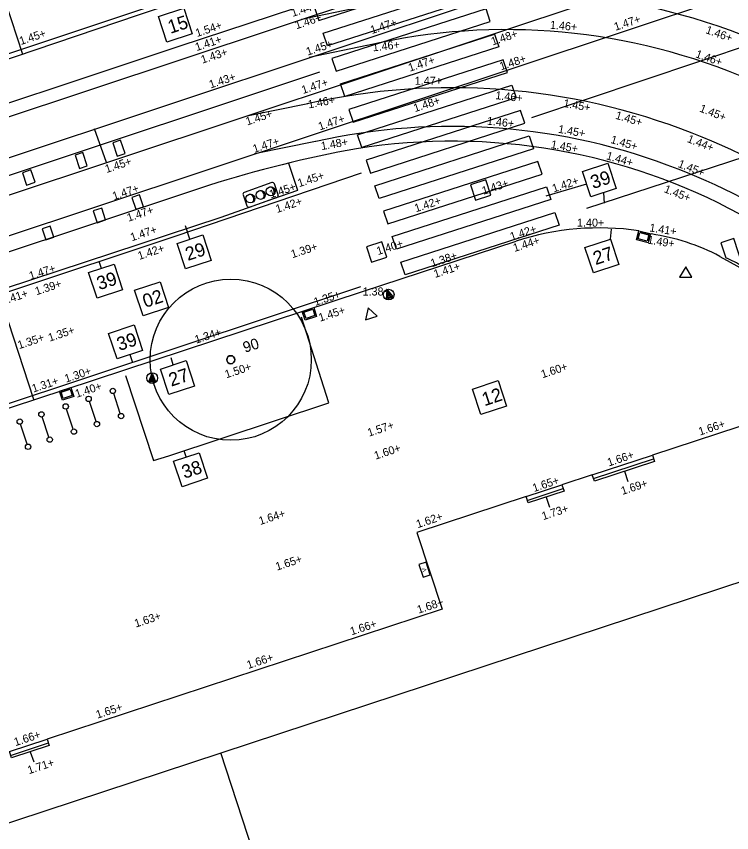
# Model space of a CAD drawing. Extents: x 122462 to 123306, y 485548 to 486417.
# Drawn here: x 122777.58 to 122804.23, y 486142.72 to 486173.11 of the extents above; entities that cross this region are included whole.
import ezdxf

# ---------------------------------------------------------------- set-up
doc = ezdxf.new("R2010")
doc.units = 0
for name, color, linetype in [('B nummers', 7, 'Continuous'), ('B-WE-AL-WERKGRENS-G', 7, 'Continuous'), ('B-WE-GR-BOOM-S', 7, 'Continuous'), ('B-WE-GR-BOOM_BOOMDIAMETER', 7, 'Continuous'), ('B-WE-KL-DATA_TELECOM_KAST-S', 7, 'Continuous'), ('B-WE-OG-HOOGTEPUNT-S', 7, 'Continuous'), ('B-WE-OG-TOPOGRAFIE_GEVELDETAIL-G', 7, 'Continuous'), ('B-WE-OG-TOPOKAART-G', 7, 'Continuous'), ('B-WE-VH-KANTOPSLUITING_TROTTOIRBAND', 7, 'Continuous'), ('Level 4', 7, 'Continuous'), ('V boomranden staal', 7, 'Continuous'), ('V Hoogtelijn', 7, 'Continuous'), ('V markering 1-1 10 cm', 7, 'Continuous'), ('V markering figuratie', 7, 'Continuous'), ('V markering ononderbroken streep 10 cm', 7, 'Continuous'), ('V materiaalscheiding algemeen', 7, 'Continuous'), ('V meubilair fietsenrek', 7, 'Continuous'), ('V meubilair trammast', 7, 'Continuous'), ('V meubilair verkeersbord', 7, 'Continuous'), ('V meubilair verkeerslicht', 7, 'Continuous'), ('V Rails', 7, 'Continuous'), ('V riool putdeksel', 7, 'Continuous'), ('V riool trottoirkolk', 7, 'Continuous'), ('V RWS-band 115-225x250 mm specie', 7, 'Continuous'), ('V trottoirband 180-200x250 mm specie', 7, 'Continuous')]:
    doc.layers.add(name, color=color, linetype=linetype)

msp = doc.modelspace()

# ---------------------------------------------------------------- linework, layer by layer
at = {"layer": 'B nummers'}
for p, q in [((122798.824, 486166.862), (122797.304, 486166.421)), ((122799.456, 486166.544), (122799.48, 486166.161)), ((122784.05, 486164.818), (122783.887, 486165.312)), ((122799.714, 486164.821), (122799.75, 486165.191)), ((122780.75, 486163.729), (122780.667, 486163.979)), ((122781.81, 486160.517), (122781.905, 486160.231)), ((122783.431, 486160.138), (122783.347, 486160.393)), ((122783.916, 486156.708), (122783.839, 486156.943))]:
    msp.add_line(p, q, dxfattribs=at)
for points in [[(122782.875, 486173.101), (122783.825, 486173.414), (122784.138, 486172.464), (122783.189, 486172.151)], [(122798.668, 486167.337), (122799.617, 486167.65), (122799.931, 486166.701), (122798.981, 486166.387)], [(122783.575, 486164.661), (122784.525, 486164.974), (122784.838, 486164.025), (122783.888, 486163.711)], [(122798.764, 486164.508), (122799.714, 486164.821), (122800.027, 486163.871), (122799.078, 486163.558)], [(122780.275, 486163.572), (122781.225, 486163.886), (122781.538, 486162.936), (122780.589, 486162.623)], [(122781.989, 486162.912), (122782.939, 486163.226), (122783.252, 486162.276), (122782.303, 486161.963)], [(122781.022, 486161.31), (122781.972, 486161.623), (122782.285, 486160.673), (122781.335, 486160.36)], [(122782.957, 486159.981), (122783.906, 486160.294), (122784.22, 486159.345), (122783.27, 486159.031)], [(122794.579, 486159.237), (122795.529, 486159.551), (122795.842, 486158.601), (122794.892, 486158.288)], [(122783.442, 486156.551), (122784.391, 486156.864), (122784.705, 486155.915), (122783.755, 486155.601)]]:
    msp.add_lwpolyline(points, close=True, dxfattribs=at)
at = {"layer": 'B-WE-AL-WERKGRENS-G'}
msp.add_lwpolyline([(122857.632, 486078.279), (122830.484, 486160.606), (122900.937, 486183.81), (122887.855, 486222.555), (122665.445, 486149.273), (122678.196, 486110.449), (122807.072, 486152.895), (122835.324, 486068.154)], dxfattribs=at)
at = {"layer": 'B-WE-GR-BOOM-S'}
for radius in [3, 0.15]:
    msp.add_circle((122785.572, 486160.329), radius, dxfattribs=at)
for start, end in [(0, 180), (180, 0)]:
    msp.add_arc((122785.572, 486160.329), 0.15, start, end, dxfattribs=at)
at = {"layer": 'B-WE-KL-DATA_TELECOM_KAST-S'}
msp.add_lwpolyline([(122792.581, 486152.704), (122792.738, 486152.229), (122793.004, 486152.317), (122792.847, 486152.792)], close=True, dxfattribs=at)
at = {"layer": 'B-WE-OG-TOPOGRAFIE_GEVELDETAIL-G'}
for p, q in [((122799.085, 486155.903), (122801.323, 486156.637)), ((122800.236, 486156.175), (122800.36, 486155.795)), ((122796.617, 486155.093), (122797.957, 486155.533)), ((122797.318, 486155.218), (122797.443, 486154.838)), ((122777.37, 486145.6), (122778.779, 486146.063)), ((122778.105, 486145.737), (122778.23, 486145.356))]:
    msp.add_line(p, q, dxfattribs=at)
for points in [[(122799.039, 486156.045), (122801.276, 486156.78), (122801.355, 486156.542), (122799.117, 486155.808)], [(122796.57, 486155.236), (122797.91, 486155.676), (122797.988, 486155.438), (122796.648, 486154.998)], [(122777.323, 486145.742), (122778.733, 486146.205), (122778.81, 486145.968), (122777.401, 486145.505)]]:
    msp.add_lwpolyline(points, close=True, dxfattribs=at)
at = {"layer": 'B-WE-OG-TOPOKAART-G'}
for points in [[(122810.445, 486142.778), (122812.82, 486143.569), (122807.709, 486158.89), (122801.277, 486156.78)], [(122799.039, 486156.045), (122797.91, 486155.675)], [(122796.57, 486155.236), (122792.499, 486153.9), (122793.442, 486151.038), (122778.732, 486146.205)]]:
    msp.add_lwpolyline(points, dxfattribs=at)
at = {"layer": 'B-WE-VH-KANTOPSLUITING_TROTTOIRBAND'}
msp.add_lwpolyline([(122800.773, 486165.127), (122801.235, 486165.011)], dxfattribs=at)
at = {"layer": 'Level 4'}
msp.add_line((122787.335, 486139.177), (122785.198, 486145.691), dxfattribs=at)
at = {"layer": 'V boomranden staal'}
msp.add_lwpolyline([(122781.649, 486159.737), (122782.696, 486156.573), (122783.267, 486156.748), (122789.225, 486158.727), (122788.206, 486161.91)], dxfattribs=at)
at = {"layer": 'V Hoogtelijn'}
for points in [[(122776.534, 486175.586), (122777.809, 486171.703)], [(122776.897, 486162.888), (122778.227, 486158.855)]]:
    msp.add_lwpolyline(points, dxfattribs=at)
at = {"layer": 'V markering 1-1 10 cm'}
msp.add_line((122732.076, 486143.681), (122790.419, 486163.059), dxfattribs=at)
msp.add_lwpolyline([(122811.233, 486170.007), (122798.828, 486165.954)], dxfattribs=at)
at = {"layer": 'V markering figuratie'}
msp.add_line((122712.845, 486143.511), (122860.885, 486192.728), dxfattribs=at)
for points in [[(122788.851, 486172.962), (122794.597, 486174.813), (122794.436, 486175.287), (122788.69, 486173.436)], [(122794.918, 486173.866), (122789.172, 486172.015), (122789.012, 486172.488), (122794.758, 486174.339)], [(122789.494, 486171.068), (122795.24, 486172.919), (122795.079, 486173.392), (122789.333, 486171.541)], [(122795.561, 486171.972), (122789.815, 486170.121), (122789.654, 486170.594), (122795.4, 486172.445)], [(122790.136, 486169.173), (122795.882, 486171.024), (122795.721, 486171.498), (122789.975, 486169.647)], [(122796.203, 486170.077), (122790.457, 486168.226), (122790.297, 486168.7), (122796.043, 486170.551)], [(122790.779, 486167.279), (122796.525, 486169.13), (122796.364, 486169.604), (122790.618, 486167.753)], [(122796.846, 486168.183), (122791.1, 486166.332), (122790.939, 486166.806), (122796.685, 486168.657)], [(122791.421, 486165.385), (122797.167, 486167.236), (122797.006, 486167.71), (122791.26, 486165.859)], [(122797.488, 486166.289), (122791.742, 486164.438), (122791.582, 486164.911), (122797.328, 486166.762)], [(122797.809, 486165.342), (122792.063, 486163.491), (122791.903, 486163.964), (122797.649, 486165.815)]]:
    msp.add_lwpolyline(points, close=True, dxfattribs=at)
for points in [[(122781.463, 486168.502), (122781.175, 486168.407), (122781.343, 486167.906), (122781.634, 486168.003), (122781.463, 486168.502)], [(122780.056, 486168.04), (122779.775, 486167.949), (122779.937, 486167.453), (122780.219, 486167.547), (122780.056, 486168.04)], [(122778.124, 486167.393), (122777.815, 486167.291), (122777.967, 486166.827), (122778.282, 486166.933), (122778.124, 486167.393)], [(122782.316, 486166.021), (122782.171, 486166.461), (122781.89, 486166.369), (122782.035, 486165.927), (122782.316, 486166.021)], [(122780.909, 486165.535), (122780.763, 486165.976), (122780.446, 486165.866), (122780.592, 486165.426), (122780.909, 486165.535)], [(122778.98, 486164.888), (122778.842, 486165.306), (122778.541, 486165.204), (122778.678, 486164.787), (122778.98, 486164.888)], [(122804.647, 486163.81), (122804.306, 486164.844), (122803.832, 486164.686), (122804.017, 486164.126)]]:
    msp.add_lwpolyline(points, dxfattribs=at)
msp.add_arc((122793.654, 486142.673), 23.824, 62.5212, 64.2182, dxfattribs=at)
at = {"layer": 'V markering ononderbroken streep 10 cm'}
for points in [[(122782.506, 486173.456), (122769.669, 486169.188), (122753.621, 486163.883), (122729.113, 486155.773)], [(122796.786, 486169.34), (122805.08, 486172.122)], [(122728.941, 486151.077), (122760.57, 486161.6), (122777.147, 486167.134), (122788.89, 486171.042)], [(122790.431, 486167.268), (122783.519, 486164.927), (122758.686, 486156.675), (122742.703, 486151.362), (122729.592, 486147.018)]]:
    msp.add_lwpolyline(points, dxfattribs=at)
at = {"layer": 'V materiaalscheiding algemeen'}
for points in [[(122780.939, 486167.673), (122780.501, 486168.929)], [(122787.717, 486167.649), (122788.063, 486166.635)], [(122784.748, 486166.814), (122780.156, 486165.287)], [(122780.156, 486165.287), (122764.259, 486160.016), (122760.446, 486158.724), (122755.663, 486157.161), (122747.256, 486154.337), (122738.577, 486151.45), (122730.117, 486148.653), (122721.549, 486145.803), (122712.998, 486142.94), (122707.935, 486141.266)]]:
    msp.add_lwpolyline(points, dxfattribs=at)
for centre, radius, start, end in [((122793.815, 486145.927), 22.535, 24.1472, 99.0789), ((122797.88, 486125.633), 43.224, 100.1554, 107.687)]:
    msp.add_arc(centre, radius, start, end, dxfattribs=at)
at = {"layer": 'V meubilair fietsenrek'}
for p, q in [((122781.456, 486158.326), (122781.21, 486159.073)), ((122780.553, 486158.028), (122780.308, 486158.776)), ((122779.699, 486157.747), (122779.453, 486158.494)), ((122778.796, 486157.449), (122778.551, 486158.197)), ((122777.989, 486157.183), (122777.743, 486157.931))]:
    msp.add_line(p, q, dxfattribs=at)
for centre in [(122781.179, 486159.168), (122780.277, 486158.871), (122778.519, 486158.292), (122779.422, 486158.589), (122777.712, 486158.026), (122781.487, 486158.231), (122780.585, 486157.933), (122779.73, 486157.652), (122778.02, 486157.088), (122778.828, 486157.354)]:
    msp.add_circle(centre, 0.1, dxfattribs=at)
at = {"layer": 'V meubilair trammast'}
for points in [[(122802.293, 486163.399), (122802.743, 486163.399), (122802.518, 486163.789)], [(122790.594, 486161.814), (122791.022, 486161.954), (122790.687, 486162.254)]]:
    msp.add_lwpolyline(points, close=True, dxfattribs=at)
at = {"layer": 'V meubilair verkeersbord'}
for points in [[(122791.615, 486162.66), (122791.375, 486162.581), (122791.395, 486162.928), (122791.593, 486162.693), (122791.417, 486162.635), (122791.422, 486162.847), (122791.525, 486162.713), (122791.459, 486162.691), (122791.459, 486162.733), (122791.445, 486162.781)], [(122782.77, 486159.507), (122782.518, 486159.507), (122782.645, 486159.83), (122782.759, 486159.545), (122782.574, 486159.545), (122782.645, 486159.745), (122782.701, 486159.585), (122782.632, 486159.585), (122782.645, 486159.625), (122782.646, 486159.675)]]:
    msp.add_lwpolyline(points, dxfattribs=at)
for centre in [(122791.453, 486162.752), (122782.645, 486159.645)]:
    msp.add_circle(centre, 0.2, dxfattribs=at)
at = {"layer": 'V meubilair verkeerslicht'}
for points in [[(122787.1, 486166.921), (122786.075, 486166.556)], [(122787.34, 486166.469), (122787.196, 486166.876)], [(122786.03, 486166.461), (122786.174, 486166.054)], [(122786.27, 486166.009), (122787.295, 486166.374)]]:
    msp.add_lwpolyline(points, dxfattribs=at)
for centre in [(122786.685, 486166.465), (122787.061, 486166.599), (122786.303, 486166.329)]:
    msp.add_circle(centre, 0.166, dxfattribs=at)
for centre, radius, start, end in [((122787.125, 486166.851), 0.075, 19.6008, 109.6008), ((122786.62, 486166.439), 0.191, 323.5512, 80.5247), ((122786.996, 486166.573), 0.191, 323.5512, 80.5247), ((122786.1, 486166.486), 0.075, 109.6008, 199.6008), ((122786.238, 486166.303), 0.191, 323.5512, 80.5247), ((122787.27, 486166.444), 0.075, 289.6008, 19.6008), ((122786.245, 486166.079), 0.075, 199.6008, 289.6008)]:
    msp.add_arc(centre, radius, start, end, dxfattribs=at)
at = {"layer": 'V Rails'}
for p, q in [((122714.919, 486148.627), (122859.557, 486196.72)), ((122715.373, 486147.26), (122860.011, 486195.354)), ((122712.39, 486144.878), (122860.43, 486194.095)), ((122790.351, 486173.434), (122788.203, 486172.994)), ((122790.639, 486172.024), (122788.491, 486171.584)), ((122788.436, 486169.86), (122786.166, 486169.397)), ((122788.724, 486168.45), (122786.454, 486167.987))]:
    msp.add_line(p, q, dxfattribs=at)
for centre, radius, start, end in [((122795.822, 486149.654), 24.402, 66.5251, 103.0007), ((122795.822, 486149.654), 22.962, 66.5251, 103.0007), ((122793.805, 486145.905), 24.549, 68.6008, 102.6648), ((122793.805, 486145.905), 23.109, 68.6008, 102.6648), ((122793.991, 486146.126), 24.276, 38.9361, 68.8275), ((122793.991, 486146.126), 22.836, 38.9361, 68.8275)]:
    msp.add_arc(centre, radius, start, end, dxfattribs=at)
at = {"layer": 'V riool putdeksel'}
for points in [[(122794.686, 486166.264), (122795.256, 486166.45), (122795.07, 486167.02), (122794.5, 486166.834)], [(122790.812, 486163.96), (122791.382, 486164.146), (122791.196, 486164.716), (122790.626, 486164.53)]]:
    msp.add_lwpolyline(points, close=True, dxfattribs=at)
at = {"layer": 'V riool trottoirkolk'}
for p, q in [((122800.686, 486164.788), (122800.771, 486165.128)), ((122800.771, 486165.128), (122801.208, 486165.018)), ((122800.82, 486165.116), (122800.818, 486165.111)), ((122800.826, 486165.099), (122800.871, 486165.087)), ((122800.871, 486165.087), (122800.903, 486165.079)), ((122800.917, 486165.091), (122800.915, 486165.086)), ((122800.941, 486165.085), (122800.94, 486165.08)), ((122801.122, 486164.679), (122800.686, 486164.788)), ((122800.947, 486165.068), (122801.025, 486165.049)), ((122801.038, 486165.061), (122801.037, 486165.056)), ((122801.062, 486165.055), (122801.061, 486165.05)), ((122801.068, 486165.038), (122801.146, 486165.018)), ((122801.208, 486165.018), (122801.122, 486164.679)), ((122801.159, 486165.03), (122801.158, 486165.025)), ((122788.232, 486162.129), (122788.66, 486162.269)), ((122788.342, 486161.796), (122788.232, 486162.129)), ((122788.28, 486162.144), (122788.281, 486162.14)), ((122788.294, 486162.133), (122788.339, 486162.148)), ((122788.339, 486162.148), (122788.37, 486162.158)), ((122788.375, 486162.176), (122788.376, 486162.171)), ((122788.399, 486162.183), (122788.4, 486162.179)), ((122788.413, 486162.172), (122788.489, 486162.197)), ((122788.494, 486162.215), (122788.495, 486162.21)), ((122788.517, 486162.222), (122788.519, 486162.218)), ((122788.532, 486162.211), (122788.608, 486162.236)), ((122788.612, 486162.254), (122788.614, 486162.249)), ((122788.66, 486162.269), (122788.769, 486161.937)), ((122788.769, 486161.937), (122788.342, 486161.796)), ((122779.189, 486159.154), (122779.616, 486159.294)), ((122779.298, 486158.821), (122779.189, 486159.154)), ((122779.236, 486159.169), (122779.238, 486159.165)), ((122779.25, 486159.158), (122779.295, 486159.173)), ((122779.295, 486159.173), (122779.326, 486159.183)), ((122779.331, 486159.201), (122779.333, 486159.196)), ((122779.355, 486159.209), (122779.357, 486159.204)), ((122779.369, 486159.197), (122779.445, 486159.222)), ((122779.45, 486159.24), (122779.452, 486159.235)), ((122779.474, 486159.248), (122779.475, 486159.243)), ((122779.488, 486159.236), (122779.564, 486159.261)), ((122779.569, 486159.279), (122779.57, 486159.274)), ((122779.616, 486159.294), (122779.726, 486158.962)), ((122779.726, 486158.962), (122779.298, 486158.821))]:
    msp.add_line(p, q, dxfattribs=at)
for points in [[(122801.086, 486164.739), (122800.747, 486164.825), (122800.807, 486165.067), (122801.147, 486164.982)], [(122788.706, 486161.969), (122788.374, 486161.859), (122788.296, 486162.097), (122788.628, 486162.206)], [(122779.663, 486158.994), (122779.33, 486158.885), (122779.252, 486159.122), (122779.584, 486159.231)]]:
    msp.add_lwpolyline(points, close=True, dxfattribs=at)
for centre, start, end in [((122800.828, 486165.108), 165.9054, 255.9054), ((122800.906, 486165.089), 255.9054, 345.9054), ((122800.949, 486165.078), 165.9054, 255.9054), ((122801.027, 486165.058), 255.9054, 345.9054), ((122801.071, 486165.047), 165.9054, 255.9054), ((122801.148, 486165.028), 255.9054, 345.9054), ((122788.291, 486162.143), 198.2066, 288.2066), ((122788.367, 486162.168), 288.2066, 18.2066), ((122788.41, 486162.182), 198.2066, 288.2066), ((122788.486, 486162.207), 288.2066, 18.2066), ((122788.528, 486162.221), 198.2066, 288.2066), ((122788.604, 486162.246), 288.2066, 18.2066), ((122779.247, 486159.168), 198.2066, 288.2066), ((122779.323, 486159.193), 288.2066, 18.2066), ((122779.366, 486159.207), 198.2066, 288.2066), ((122779.442, 486159.232), 288.2066, 18.2066), ((122779.485, 486159.246), 198.2066, 288.2066), ((122779.561, 486159.271), 288.2066, 18.2066)]:
    msp.add_arc(centre, 0.01, start, end, dxfattribs=at)
at = {"layer": 'V RWS-band 115-225x250 mm specie'}
msp.add_lwpolyline([(122788.059, 486166.632), (122787.124, 486166.306), (122785.206, 486165.623), (122777.128, 486162.968), (122760.015, 486157.342), (122740.955, 486150.951), (122719.987, 486144.031), (122708.301, 486140.155)], dxfattribs=at)
at = {"layer": 'V trottoirband 180-200x250 mm specie'}
for points in [[(122764.995, 486167.464), (122774.458, 486170.57), (122782.134, 486173.165), (122791.772, 486176.363), (122801.583, 486179.598)], [(122802.843, 486178.897), (122803.005, 486178.403), (122796.653, 486176.321), (122790.145, 486174.137), (122787.981, 486173.414), (122783.643, 486171.985), (122782.562, 486171.633), (122774.188, 486168.85), (122765.631, 486166.001), (122757.287, 486163.217), (122748.482, 486160.287), (122740.076, 486157.459), (122731.818, 486154.747)], [(122790.481, 486162.869), (122796.203, 486164.742)], [(122803.794, 486164.177), (122806.455, 486162.709)], [(122772.378, 486156.913), (122779.402, 486159.225), (122790.481, 486162.869)]]:
    msp.add_lwpolyline(points, dxfattribs=at)
for centre, radius, start, end in [((122799.308, 486155.205), 10.03, 81.5995, 108.0315), ((122800.038, 486156.995), 8.104, 62.3906, 81.5069)]:
    msp.add_arc(centre, radius, start, end, dxfattribs=at)

# ---------------------------------------------------------------- texts
at = {"layer": 'B nummers'}
for s, p in [('15', (122783.322, 486172.458)), ('39', (122799.066, 486166.679)), ('29', (122783.973, 486164.003)), ('27', (122799.163, 486163.849)), ('39', (122780.673, 486162.914)), ('02', (122782.387, 486162.254)), ('39', (122781.42, 486160.651)), ('27', (122783.355, 486159.323)), ('12', (122795.024, 486158.595)), ('38', (122783.84, 486155.893))]:
    msp.add_text(s, height=0.5, rotation=18.2603, dxfattribs=at).set_placement(p)
at = {"layer": 'B-WE-GR-BOOM_BOOMDIAMETER'}
msp.add_text('90', height=0.4, rotation=17.9781, dxfattribs=at).set_placement((122786.099, 486160.584))
at = {"layer": 'B-WE-KL-DATA_TELECOM_KAST-S'}
msp.add_text('V', height=0.16, rotation=108.2365, dxfattribs=at).set_placement((122792.88, 486152.461))
at = {"layer": 'B-WE-OG-HOOGTEPUNT-S'}
for s, rotation, p in [('1.44+', 18.3786, (122787.878, 486173.088)), ('1.46+', 18.3414, (122788.02, 486172.629)), ('1.47+', 18.3717, (122799.905, 486172.572)), ('1.54+', 18.3786, (122784.312, 486172.339)), ('1.47+', 18.3414, (122790.827, 486172.448)), ('1.46+', 354.9852, (122797.452, 486172.653)), ('1.46+', 340.697, (122803.238, 486172.49)), ('1.45+', 18.4074, (122777.752, 486172.042)), ('1.48+', 18.371, (122795.324, 486172.024)), ('1.41+', 18.3786, (122784.302, 486171.816)), ('1.45+', 18.3414, (122788.435, 486171.646)), ('1.46+', 6.4053, (122790.871, 486171.807)), ('1.43+', 18.3786, (122784.517, 486171.347)), ('1.46+', 340.697, (122802.86, 486171.592)), ('1.47+', 18.3718, (122792.241, 486171.048)), ('1.48+', 18.371, (122795.639, 486171.099)), ('1.43+', 18.3786, (122784.821, 486170.423)), ('1.47+', 18.3718, (122788.264, 486170.218)), ('1.46+', 353.6293, (122795.418, 486170.032)), ('1.46+', 10.6368, (122788.476, 486169.681)), ('1.48+', 18.3718, (122792.435, 486169.544)), ('1.45+', 349.7649, (122797.945, 486169.743)), ('1.45+', 338.653, (122803.008, 486169.573)), ('1.45+', 18.3718, (122786.185, 486169.047)), ('1.47+', 18.3745, (122788.887, 486168.861)), ('1.46+', 353.6293, (122795.104, 486169.082)), ('1.45+', 343.6105, (122799.879, 486169.303)), ('1.45+', 349.7649, (122797.748, 486168.782)), ('1.47+', 18.3718, (122786.447, 486168.024)), ('1.48+', 9.9863, (122788.956, 486168.131)), ('1.45+', 349.7649, (122797.479, 486168.209)), ('1.45+', 343.6105, (122799.7, 486168.402)), ('1.44+', 338.653, (122802.548, 486168.439)), ('1.44+', 343.6105, (122799.536, 486167.798)), ('1.45+', 18.4023, (122780.943, 486167.276)), ('1.45+', 338.653, (122802.205, 486167.509)), ('1.45+', 18.5122, (122788.118, 486166.75)), ('1.43+', 18.125, (122794.982, 486166.466)), ('1.42+', 18.125, (122797.6, 486166.553)), ('1.47+', 18.4023, (122781.218, 486166.267)), ('1.45+', 18.125, (122787.062, 486166.334)), ('1.45+', 338.653, (122801.687, 486166.572)), ('1.42+', 18.125, (122787.298, 486165.79)), ('1.42+', 18.125, (122792.469, 486165.815)), ('1.47+', 18.4023, (122781.761, 486165.463)), ('1.41+', 351.1237, (122801.151, 486165.108)), ('1.47+', 18.4023, (122781.888, 486164.735)), ('1.42+', 18.125, (122796.028, 486164.761)), ('1.44+', 18.125, (122796.143, 486164.338)), ('1.49+', 351.1237, (122801.079, 486164.654)), ('1.42+', 18.4023, (122782.164, 486164.043)), ('1.39+', 18.125, (122787.868, 486164.106)), ('1.40+', 18.125, (122791.058, 486164.221)), ('1.38+', 18.125, (122793.07, 486163.77)), ('1.41+', 18.125, (122793.185, 486163.372)), ('1.47+', 18.1942, (122778.113, 486163.298)), ('1.39+', 18.1942, (122778.334, 486162.725)), ('1.41+', 18.2066, (122777.083, 486162.361)), ('1.35+', 18.125, (122788.72, 486162.329)), ('1.45+', 18.125, (122788.897, 486161.742)), ('1.35+', 18.1942, (122778.823, 486160.998)), ('1.34+', 18.2066, (122784.285, 486160.925)), ('1.35+', 18.2066, (122777.687, 486160.721)), ('1.30+', 18.1942, (122779.438, 486159.474)), ('1.50+', 18.2066, (122785.405, 486159.632)), ('1.60+', 18.187, (122797.183, 486159.638)), ('1.31+', 18.2066, (122778.22, 486159.105)), ('1.40+', 18.1942, (122779.833, 486158.91)), ('1.57+', 18.187, (122790.719, 486157.461)), ('1.66+', 18.187, (122803.05, 486157.504)), ('1.60+', 18.187, (122790.968, 486156.607)), ('1.66+', 18.187, (122799.653, 486156.353)), ('1.65+', 18.187, (122796.867, 486155.403)), ('1.69+', 18.187, (122800.163, 486155.294)), ('1.73+', 18.187, (122797.212, 486154.355)), ('1.64+', 18.1571, (122786.67, 486154.174)), ('1.62+', 18.187, (122792.534, 486154.056)), ('1.65+', 18.1571, (122787.294, 486152.476)), ('1.68+', 18.187, (122792.566, 486150.872)), ('1.63+', 18.1571, (122782.037, 486150.357)), ('1.66+', 18.187, (122790.072, 486150.066)), ('1.66+', 18.1571, (122786.224, 486148.815)), ('1.65+', 18.187, (122780.604, 486146.964)), ('1.66+', 18.187, (122777.552, 486145.943)), ('1.71+', 18.187, (122778.057, 486144.899))]:
    msp.add_text(s, height=0.3, rotation=rotation, dxfattribs=at).set_placement(p)
for s, p in [('1.47+', (122792.426, 486170.565)), ('1.40+', (122798.469, 486165.281)), ('1.38+', (122790.481, 486162.719))]:
    msp.add_text(s, height=0.3, dxfattribs=at).set_placement(p)

doc.saveas('drawing.dxf')
